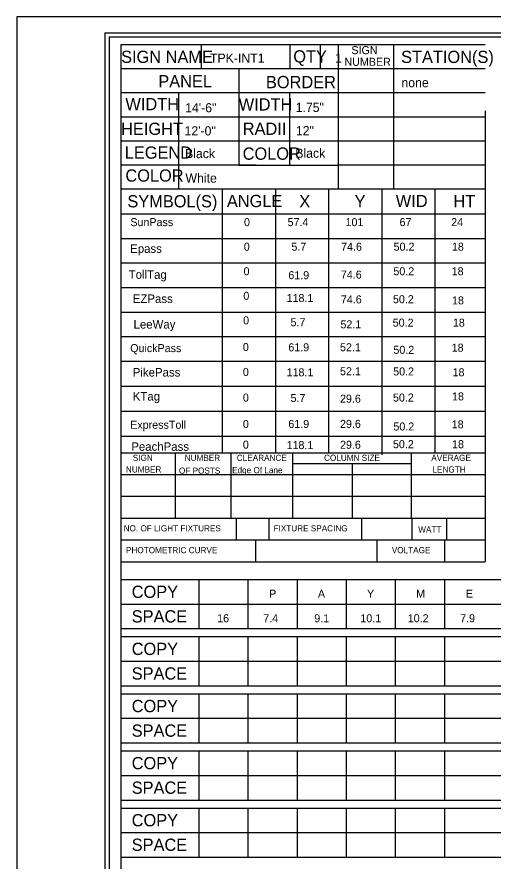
# Model space of a CAD drawing. Extents: x 17890459 to 17890580, y 17897938 to 17898017.
# Drawn here: x 17890458.91 to 17890480.8, y 17897978.61 to 17898017.37 of the extents above; entities that cross this region are included whole.
import ezdxf

# ---------------------------------------------------------------- set-up
doc = ezdxf.new("R2010")
doc.units = 0
for name, color, linetype in [('GSSign', 7, 'Continuous'), ('PlotBorder_dp', 7, 'Continuous'), ('SheetBorder_dp', 7, 'Continuous'), ('SheetLinesMisc2_dp', 7, 'Continuous'), ('TextMinor', 7, 'Continuous')]:
    doc.layers.add(name, color=color, linetype=linetype)

msp = doc.modelspace()

# ---------------------------------------------------------------- linework, layer by layer
at = {"layer": 'PlotBorder_dp'}
msp.add_lwpolyline([(17890458.908, 17897939.544), (17890580.045, 17897939.544), (17890580.045, 17898017.365), (17890458.908, 17898017.365)], close=True, dxfattribs=at)
at = {"layer": 'SheetBorder_dp'}
for q in [(17890462.946, 17897940.278), (17890576.007, 17898016.631)]:
    msp.add_line((17890462.946, 17898016.631), q, dxfattribs=at)
at = {"layer": 'SheetLinesMisc2_dp'}
for p, q in [((17890463.151, 17898016.456), (17890575.98, 17898016.456)), ((17890463.151, 17898016.456), (17890463.151, 17897946.221)), ((17890463.151, 17898016.456), (17890575.98, 17898016.456)), ((17890463.699, 17897991.536), (17890463.699, 17898016.096)), ((17890463.699, 17898016.096), (17890480.428, 17898016.096)), ((17890467.386, 17898016.096), (17890467.386, 17898014.992)), ((17890471.453, 17898016.096), (17890471.453, 17898014.992)), ((17890472.842, 17898016.096), (17890472.842, 17898014.992)), ((17890473.67, 17898016.096), (17890473.67, 17898009.472)), ((17890476.215, 17898016.096), (17890476.215, 17898009.472)), ((17890463.699, 17898014.992), (17890480.428, 17898014.992)), ((17890469.105, 17898014.992), (17890469.105, 17898010.564)), ((17890463.699, 17898013.888), (17890480.428, 17898013.888)), ((17890466.342, 17898013.888), (17890466.342, 17898009.472)), ((17890471.438, 17898013.876), (17890471.438, 17898010.564)), ((17890463.699, 17898012.784), (17890480.428, 17898012.784)), ((17890480.428, 17898013.047), (17890480.428, 17897992.352)), ((17890463.699, 17898011.68), (17890480.428, 17898011.68)), ((17890463.699, 17898010.576), (17890469.903, 17898010.576)), ((17890469.105, 17898010.564), (17890473.67, 17898010.564)), ((17890473.67, 17898010.576), (17890480.428, 17898010.576)), ((17890463.699, 17898009.472), (17890480.428, 17898009.472)), ((17890468.345, 17898009.45), (17890468.345, 17897997.36)), ((17890470.789, 17898009.45), (17890470.789, 17897997.36)), ((17890473.234, 17898009.45), (17890473.234, 17897997.36)), ((17890475.678, 17898009.45), (17890475.678, 17897997.264)), ((17890478.122, 17898009.45), (17890478.122, 17897997.36)), ((17890463.702, 17898008.323), (17890480.428, 17898008.323)), ((17890463.702, 17898007.195), (17890480.428, 17898007.195)), ((17890463.702, 17898006.068), (17890480.428, 17898006.068)), ((17890463.702, 17898004.941), (17890480.428, 17898004.941)), ((17890463.702, 17898003.813), (17890480.428, 17898003.813)), ((17890463.702, 17898002.686), (17890480.428, 17898002.686)), ((17890463.702, 17898001.558), (17890480.428, 17898001.558)), ((17890463.699, 17898000.409), (17890480.428, 17898000.409)), ((17890463.695, 17897999.26), (17890480.424, 17897999.26)), ((17890463.691, 17897998.111), (17890480.421, 17897998.111)), ((17890463.699, 17897997.36), (17890480.428, 17897997.36)), ((17890466.181, 17897997.36), (17890466.181, 17897994.355)), ((17890468.747, 17897997.36), (17890468.747, 17897994.355)), ((17890471.58, 17897997.36), (17890471.58, 17897994.355)), ((17890477.036, 17897997.36), (17890477.036, 17897994.355)), ((17890471.58, 17897996.87), (17890477.032, 17897996.87)), ((17890474.319, 17897996.87), (17890474.319, 17897994.355)), ((17890463.699, 17897996.358), (17890480.428, 17897996.358)), ((17890463.699, 17897995.357), (17890480.428, 17897995.357)), ((17890463.699, 17897994.355), (17890480.428, 17897994.355)), ((17890468.992, 17897994.355), (17890468.992, 17897993.354)), ((17890470.487, 17897994.355), (17890470.487, 17897993.354)), ((17890474.743, 17897994.355), (17890474.743, 17897993.354)), ((17890477.058, 17897994.355), (17890477.058, 17897993.354)), ((17890478.655, 17897994.355), (17890478.655, 17897993.354)), ((17890463.699, 17897993.354), (17890480.428, 17897993.354)), ((17890469.87, 17897993.354), (17890469.87, 17897992.352)), ((17890475.452, 17897993.354), (17890475.452, 17897992.352)), ((17890478.558, 17897993.354), (17890478.558, 17897992.352)), ((17890463.699, 17897992.352), (17890480.428, 17897992.352)), ((17890463.699, 17897991.536), (17890519.188, 17897991.536)), ((17890463.699, 17897947.331), (17890463.699, 17897991.536)), ((17890467.271, 17897991.536), (17890467.271, 17897989.281)), ((17890469.528, 17897991.536), (17890469.528, 17897989.281)), ((17890471.786, 17897991.536), (17890471.786, 17897989.281)), ((17890474.042, 17897991.536), (17890474.042, 17897989.281)), ((17890476.3, 17897991.536), (17890476.3, 17897989.281)), ((17890478.557, 17897991.536), (17890478.557, 17897989.281)), ((17890463.699, 17897990.408), (17890519.188, 17897990.408)), ((17890463.699, 17897989.281), (17890519.188, 17897989.281)), ((17890463.699, 17897988.914), (17890519.188, 17897988.914)), ((17890467.271, 17897988.914), (17890467.271, 17897986.659)), ((17890469.528, 17897988.914), (17890469.528, 17897986.659)), ((17890471.786, 17897988.914), (17890471.786, 17897986.659)), ((17890474.042, 17897988.914), (17890474.042, 17897986.659)), ((17890476.3, 17897988.914), (17890476.3, 17897986.659)), ((17890478.557, 17897988.914), (17890478.557, 17897986.659)), ((17890463.699, 17897987.786), (17890519.188, 17897987.786)), ((17890463.699, 17897986.659), (17890519.188, 17897986.659)), ((17890463.699, 17897986.291), (17890519.188, 17897986.291)), ((17890467.271, 17897986.291), (17890467.271, 17897984.037)), ((17890469.528, 17897986.291), (17890469.528, 17897984.037)), ((17890471.786, 17897986.291), (17890471.786, 17897984.037)), ((17890474.042, 17897986.291), (17890474.042, 17897984.037)), ((17890476.3, 17897986.291), (17890476.3, 17897984.037)), ((17890478.557, 17897986.291), (17890478.557, 17897984.037)), ((17890463.699, 17897985.165), (17890519.188, 17897985.165)), ((17890463.699, 17897984.037), (17890519.188, 17897984.037)), ((17890463.699, 17897983.669), (17890519.188, 17897983.669)), ((17890467.271, 17897983.669), (17890467.271, 17897981.415)), ((17890469.528, 17897983.669), (17890469.528, 17897981.415)), ((17890471.786, 17897983.669), (17890471.786, 17897981.415)), ((17890474.042, 17897983.669), (17890474.042, 17897981.415)), ((17890476.3, 17897983.669), (17890476.3, 17897981.415)), ((17890478.557, 17897983.669), (17890478.557, 17897981.415)), ((17890463.699, 17897982.543), (17890519.188, 17897982.543)), ((17890463.699, 17897981.415), (17890519.188, 17897981.415)), ((17890463.699, 17897981.048), (17890519.188, 17897981.048)), ((17890467.271, 17897981.048), (17890467.271, 17897978.794)), ((17890469.528, 17897981.048), (17890469.528, 17897978.794)), ((17890471.786, 17897981.048), (17890471.786, 17897978.794)), ((17890474.042, 17897981.048), (17890474.042, 17897978.794)), ((17890476.3, 17897981.048), (17890476.3, 17897978.794)), ((17890478.557, 17897981.048), (17890478.557, 17897978.794)), ((17890463.699, 17897979.92), (17890519.188, 17897979.921)), ((17890463.699, 17897978.794), (17890519.188, 17897978.794))]:
    msp.add_line(p, q, dxfattribs=at)

# ---------------------------------------------------------------- texts
at = {"layer": 'GSSign'}
for s, height, p in [('TPK-INT1', 0.4218, (17890467.784, 17898015.262)), ('1', 0.422, (17890473.531, 17898015.261)), ('none', 0.4218, (17890476.584, 17898014.136)), ('14\'-6"', 0.4218, (17890466.643, 17898012.982)), ('1.75"', 0.4218, (17890471.722, 17898012.998)), ('12\'-0"', 0.4218, (17890466.614, 17898011.922)), ('12"', 0.4218, (17890471.733, 17898011.934)), ('Black', 0.4218, (17890466.638, 17898010.882)), ('Black', 0.4218, (17890471.705, 17898010.898)), ('White', 0.4218, (17890466.657, 17898009.754)), ('SunPass', 0.3676, (17890464.125, 17898007.759)), ('0', 0.368, (17890469.347, 17898007.759)), ('57.4', 0.3676, (17890471.352, 17898007.759)), ('101', 0.3676, (17890474.013, 17898007.759)), ('67', 0.3676, (17890476.497, 17898007.759)), ('24', 0.3676, (17890478.87, 17898007.759)), ('Epass', 0.3921, (17890464.115, 17898006.532)), ('0', 0.368, (17890469.337, 17898006.632)), ('5.7', 0.3676, (17890471.526, 17898006.632)), ('74.6', 0.3676, (17890473.81, 17898006.632)), ('50.2', 0.3676, (17890476.224, 17898006.632)), ('18', 0.3676, (17890478.904, 17898006.632)), ('TollTag', 0.3921, (17890464.049, 17898005.341)), ('0', 0.368, (17890469.327, 17898005.504)), ('61.9', 0.3676, (17890471.385, 17898005.324)), ('74.6', 0.3676, (17890473.8, 17898005.35)), ('50.2', 0.3676, (17890476.214, 17898005.504)), ('18', 0.3676, (17890478.894, 17898005.504)), ('EZPass', 0.3921, (17890464.236, 17898004.23)), ('0', 0.368, (17890469.317, 17898004.377)), ('118.1', 0.3676, (17890471.305, 17898004.276)), ('74.6', 0.3676, (17890473.8, 17898004.212)), ('50.2', 0.3676, (17890476.194, 17898004.221)), ('18', 0.3676, (17890478.91, 17898004.167)), ('LeeWay', 0.3921, (17890464.271, 17898003.056)), ('0', 0.368, (17890469.307, 17898003.25)), ('5.7', 0.3676, (17890471.486, 17898003.163)), ('52.1', 0.3676, (17890473.78, 17898003.067)), ('50.2', 0.3676, (17890476.183, 17898003.145)), ('18', 0.3676, (17890478.948, 17898003.145)), ('QuickPass', 0.3676, (17890464.118, 17898001.976)), ('0', 0.368, (17890469.296, 17898002.027)), ('61.9', 0.3676, (17890471.385, 17898002.014)), ('52.1', 0.3676, (17890473.761, 17898002.017)), ('50.2', 0.3676, (17890476.214, 17898001.897)), ('18', 0.3676, (17890478.894, 17898001.996)), ('PikePass', 0.3921, (17890464.236, 17898000.854)), ('0', 0.368, (17890469.296, 17898000.883)), ('118.1', 0.3676, (17890471.305, 17898000.863)), ('52.1', 0.3676, (17890473.761, 17898000.915)), ('50.2', 0.3676, (17890476.204, 17898000.905)), ('18', 0.3676, (17890478.935, 17898000.867)), ('KTag', 0.3921, (17890464.236, 17897999.752)), ('0', 0.368, (17890469.296, 17897999.705)), ('5.7', 0.3676, (17890471.486, 17897999.687)), ('29.6', 0.3676, (17890473.761, 17897999.655)), ('50.2', 0.3676, (17890476.194, 17897999.706)), ('18', 0.3676, (17890478.91, 17897999.758)), ('ExpressToll', 0.36762, (17890464.118, 17897998.457)), ('0', 0.368, (17890469.296, 17897998.493)), ('61.9', 0.3676, (17890471.385, 17897998.494)), ('29.6', 0.3676, (17890473.761, 17897998.498)), ('50.2', 0.3676, (17890476.214, 17897998.378)), ('18', 0.3676, (17890478.894, 17897998.476)), ('PeachPass', 0.3921, (17890464.167, 17897997.445)), ('0', 0.368, (17890469.296, 17897997.545)), ('118.1', 0.3676, (17890471.305, 17897997.524)), ('29.6', 0.3676, (17890473.761, 17897997.54)), ('50.2', 0.3676, (17890476.194, 17897997.566)), ('18', 0.3676, (17890478.91, 17897997.566)), ('P', 0.368, (17890470.503, 17897990.702)), ('P', 0.368, (17890470.503, 17897990.702)), ('A', 0.368, (17890472.744, 17897990.702)), ('A', 0.368, (17890472.744, 17897990.702)), ('Y', 0.368, (17890475.001, 17897990.702)), ('Y', 0.368, (17890475.001, 17897990.702)), ('M', 0.368, (17890477.259, 17897990.702)), ('M', 0.368, (17890477.259, 17897990.702)), ('E', 0.368, (17890479.543, 17897990.702)), ('E', 0.368, (17890479.543, 17897990.702)), ('16', 0.3676, (17890468.114, 17897989.575)), ('16', 0.3676, (17890468.114, 17897989.575)), ('7.4', 0.3676, (17890470.232, 17897989.575)), ('7.4', 0.3676, (17890470.232, 17897989.575)), ('9.1', 0.3676, (17890472.577, 17897989.575)), ('9.1', 0.3676, (17890472.577, 17897989.575)), ('10.1', 0.3676, (17890474.695, 17897989.575)), ('10.1', 0.3676, (17890474.695, 17897989.575)), ('10.2', 0.3676, (17890476.874, 17897989.575)), ('10.2', 0.3676, (17890476.874, 17897989.575)), ('7.9', 0.3676, (17890479.281, 17897989.575)), ('7.9', 0.3676, (17890479.281, 17897989.575))]:
    msp.add_text(s, height=height, dxfattribs=at).set_placement(p)
at = {"layer": 'TextMinor'}
for s, height, p in [('SIGN NAME', 0.5624, (17890463.699, 17898015.251)), ('QTY', 0.5624, (17890471.613, 17898015.27)), ('SIGN', 0.3676, (17890474.284, 17898015.654)), ('STATION(S)', 0.5624, (17890476.567, 17898015.248)), ('NUMBER', 0.3676, (17890473.965, 17898015.119)), ('PANEL', 0.5624, (17890465.409, 17898014.129)), ('BORDER', 0.5624, (17890470.356, 17898014.091)), ('WIDTH', 0.5624, (17890463.897, 17898013.079)), ('WIDTH', 0.5624, (17890469.105, 17898013.067)), ('HEIGHT', 0.5624, (17890463.699, 17898011.947)), ('RADII', 0.5624, (17890469.29, 17898011.949)), ('LEGEND', 0.5624, (17890463.868, 17898010.855)), ('COLOR', 0.5624, (17890469.286, 17898010.807)), ('COLOR', 0.5624, (17890463.897, 17898009.801)), ('SYMBOL(S)', 0.5624, (17890463.987, 17898008.621)), ('ANGLE', 0.5624, (17890468.56, 17898008.633)), ('X', 0.562, (17890471.889, 17898008.621)), ('Y', 0.562, (17890474.431, 17898008.621)), ('WID', 0.5624, (17890476.324, 17898008.633)), ('HT', 0.5624, (17890478.973, 17898008.622)), ('SIGN', 0.2812, (17890464.235, 17897996.984)), ('NUMBER', 0.2812, (17890466.622, 17897996.981)), ('CLEARANCE', 0.2812, (17890469.017, 17897996.983)), ('COLUMN SIZE', 0.28123, (17890473.025, 17897996.983)), ('AVERAGE', 0.2812, (17890477.957, 17897996.983)), ('NUMBER', 0.2812, (17890463.92, 17897996.449)), ('OF POSTS', 0.2812, (17890466.357, 17897996.396)), ('Edge Of Lane', 0.28123, (17890468.8, 17897996.417)), ('LENGTH', 0.2812, (17890478.011, 17897996.449)), ('NO. OF LIGHT FIXTURES', 0.28114, (17890463.814, 17897993.748)), ('FIXTURE SPACING', 0.28114, (17890470.707, 17897993.748)), ('WATT', 0.2811, (17890477.356, 17897993.692)), ('PHOTOMETRIC CURVE', 0.28114, (17890463.924, 17897992.746)), ('VOLTAGE', 0.2811, (17890476.141, 17897992.746)), ('COPY', 0.5625, (17890464.186, 17897990.692)), ('SPACE', 0.5625, (17890464.186, 17897989.565)), ('COPY', 0.5625, (17890464.186, 17897988.071)), ('SPACE', 0.5625, (17890464.186, 17897986.943)), ('COPY', 0.5625, (17890464.186, 17897985.448)), ('SPACE', 0.5625, (17890464.186, 17897984.321)), ('COPY', 0.5625, (17890464.186, 17897982.827)), ('SPACE', 0.5625, (17890464.186, 17897981.7)), ('COPY', 0.5625, (17890464.186, 17897980.207)), ('SPACE', 0.5625, (17890464.186, 17897979.08))]:
    msp.add_text(s, height=height, dxfattribs=at).set_placement(p)

doc.saveas('drawing.dxf')
